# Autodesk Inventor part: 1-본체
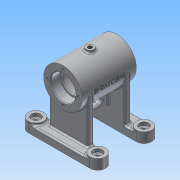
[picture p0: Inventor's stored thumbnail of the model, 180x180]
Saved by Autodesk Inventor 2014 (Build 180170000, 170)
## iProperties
Created: 2015-11
Part Number: 1-본체
Material: 알루미늄 6061
Document SubType Name: Modeling
Designer: 103-09
Density: 2.71 g/cm^3
Appearance: 알루미늄 - 평지
Mass: 359.022 g
Surface Area: 459.449 cm^2
Volume: 132.48 cm^3
Author: 103-09
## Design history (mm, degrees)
sketch "스케치1"
  geometry: L1 (-40, 0)-(40, 0); L2 (-40, 20)-(40, 20); L3 (40, 40)-(-40, 40); L4 (-40, -40)-(40, -40); L5 (40, -20)-(-40, -20); A1 r 10 centre (40, 30) between (40, 20) and (40, 40); A2 r 10 centre (-40, 30) between (-40, 40) and (-40, 20); A3 r 10 centre (40, -30) between (40, -40) and (40, -20); A4 r 10 centre (-40, -30) between (-40, -20) and (-40, -40); 2 further points
  constraints: 10 end point, 8 point on circle, 8 tangent, 4 centre point, 3 parallel, 2 coincident, 1 horizontal, 1 midpoint, 1 vertical alignment
  dimensions: "d2" = 80 distance of A1.centre A2.centre; "d3" = 40 horizontal distance of point (0, 0) A2.centre; "d4" = 20 distance between parallel lines of L2 L3; "d5" = 40 distance between parallel lines of L1 L3; "d6" = 80 distance of A3.centre A4.centre; "d7" = 20 distance between parallel lines of L4 L5; "d8" = 40 distance between parallel lines of L1 L4
extrude "돌출1" new body sketch "스케치1" distance "d9" = 10; taper "d10" = 0 deg
sketch "스케치2"
  geometry: L1 (-40, 20)-(40, 20) reference; L2 (40, 40)-(-40, 40) reference; C1 r 10 at (-40, -30); C2 r 10 at (40, -30); C3 r 10 at (40, 30); C4 r 10 at (-40, 30); A1 r 10 centre (40, -30) between (40, -40) and (40, -20) reference; A2 r 10 centre (-40, -30) between (-40, -20) and (-40, -40) reference; A3 r 10 centre (40, 30) between (40, 20) and (40, 40) reference; A4 r 10 centre (-40, 30) between (-40, 40) and (-40, 20) reference; 1 further point
  constraints: 4 centre point, 4 coincident, 3 equal radius
  dimensions: "d91" = 20 diameter of C4
extrude "돌출2" join sketch "스케치2" distance "d11" = 3; taper "d12" = 0 deg
node "작업 평면1"
sketch "스케치3"
  geometry: L1 (-35, 68)-(35, 68); L2 (-20, 0)-(-40, 0) reference; L3 (-35, 84)-(-23, 84); L4 (-23, 84)-(-23, 82); L5 (-23, 82)-(-21, 82); L6 (-21, 82)-(-21, 89); L7 (-21, 89)-(21, 89); L8 (21, 89)-(21, 82); L9 (21, 82)-(23, 82); L10 (23, 82)-(23, 84); L11 (23, 84)-(35, 84); L12 (35, 84)-(35, 93); L13 (35, 93)-(-35, 93); L14 (-35, 93)-(-35, 84); 2 further points
  constraints: 26 end point, 10 parallel, 3 collinear, 3 vertical alignment, 1 horizontal, 1 midpoint, 1 perpendicular
  dimensions: "d14" = 68 distance between parallel lines of L1 L2; "d15" = 50 diameter of L13 L1; "d16" = 32 diameter of L11 L1; "d17" = 28 diameter of L9 L1; "d18" = 42 diameter of L7 L1; "d19" = 12 distance of L3.start L3.end; "d20" = 70 distance of L12.end L13.end; "d22" = 12 distance of L10.end L11.end; "d23" = 2 distance of L4.end L5.end; "d24" = 42 distance of L6.end L7.end
revolve "회전1" sketch "스케치3" stored, may be unused: angle "d25" = 90 deg
sketch "스케치4"
  geometry: L1 (40, 40)-(-40, 40) reference; L2 (-40, 20)-(40, 20) reference; L3 (-25, 20)-(25, 20); L4 (25, 20)-(25, 28); L5 (25, 28)-(-25, 28); L6 (-25, 28)-(-25, 20); L7 (-40, -40)-(40, -40) reference; L8 (40, -20)-(-40, -20) reference; L9 (-25, -20)-(25, -20); L10 (25, -20)-(25, -28); L11 (25, -28)-(-25, -28); L12 (-25, -28)-(-25, -20); L13 (-4, 20)-(4, 20); L14 (4, -20)-(-4, -20); A1 r 10 centre (-40, -30) between (-40, -20) and (-40, -40) reference; A2 r 10 centre (40, -30) between (40, -40) and (40, -20) reference; 6 further points
  constraints: 20 end point, 5 midpoint, 5 parallel, 3 horizontal, 3 point on line, 3 vertical alignment, 2 equal length, 2 perpendicular, 1 coincident
  dimensions: "d26" = 50 distance of L4.end L5.end; "d27" = 8 distance of L5.end L3.start
extrude "돌출3" join sketch "스케치4" stored distance "d29" = 3; taper "d30" = 0 deg
node "작업 평면4"
sketch "스케치6"
  geometry: L1 (25, 28)-(25, 20) reference; L2 (25, 20)-(-25, 20) reference; L3 (-25, 20)-(-25, 28) reference; L4 (-25, 28)-(25, 28) reference; L5 (25, -20)-(25, -28) reference; L6 (25, -28)-(-25, -28) reference; L7 (-25, -28)-(-25, -20) reference; L8 (-25, -20)-(25, -20) reference; L9 (-4, 20)-(4, 20); L10 (4, 20)-(4, -20); L11 (4, -20)-(-4, -20); L12 (-4, -20)-(-4, 20); 2 further points
  constraints: 8 end point, 2 parallel, 2 point on line, 1 horizontal, 1 midpoint, 1 perpendicular, 1 vertical alignment
  dimensions: "d36" = 8 distance of L9.start L9.end
extrude "돌출5" join sketch "스케치6" stored distance "d37" = 8; taper "d38" = 0 deg
sketch "스케치7"
  geometry: L1 (-20.322, 40)-(0, 40) reference; L2 (-13.5, 12)-(-13.5, 28); L3 (-6.5, 28)-(-6.5, 12); L4 (23, 60)-(23, 40) reference; A1 r 3.5 centre (-10, 28) between (-6.5, 28) and (-13.5, 28); A2 r 3.5 centre (-10, 12) between (-13.5, 12) and (-6.5, 12); 2 further points
  constraints: 4 end point, 4 point on circle, 4 tangent, 2 centre point, 1 horizontal alignment, 1 midpoint, 1 parallel, 1 perpendicular
  dimensions: "d39" = 23 dimension on A1 A2; "d40" = 33 distance from line of A1.centre L4; "d41" = 3.5 radius of A1
extrude "돌출6" cut sketch "스케치7" stored distance "d42" = 8; taper "d43" = 0 deg
node "작업 평면5"
sketch "스케치8"
  geometry: C1 r 5 at (0, 0); 1 further point
  constraints: 1 centre point, 1 coincident
  dimensions: "d45" = 10 diameter of C1
extrude "돌출7" join sketch "스케치8" stored distance "d46" = 8; taper "d47" = 0 deg
node "작업 평면6"
sketch "스케치9"
  geometry: L1 (-4, 23)-(-4, 29.5) reference; L2 (-4, 29.5)-(4, 29.5) reference; L3 (4, 29.5)-(4, 23) reference; L4 (4, 23)-(-4, 23) reference; L5 (-4, 36.5)-(-4, 43.322) reference; L6 (-5, 92.495)-(-5, 96) reference; L7 (-5, 96)-(5, 96) reference; L8 (5, 96)-(5, 92.495) reference; L9 (4, 43.322)-(4, 36.5) reference; L10 (4, 36.5)-(-4, 36.5) reference; L11 (0, 68)-(0, 47); L12 (0, 68)-(14, 43.751); A1 r 25 centre (0, 68) between (-5, 92.495) and (-4, 43.322) reference; A2 r 25 centre (0, 68) between (4, 43.322) and (5, 92.495) reference; 1 further point
  constraints: 4 end point, 1 perpendicular, 1 vertical alignment, 1 other
  dimensions: "d49" = 30 deg angle of L12 L11; "d50" = 28 distance of L11.start L12.end
  node "절단 모서리 투영2"
node "작업 평면7"
sketch "스케치10"
  geometry: C1 r 6 at (0, 0); 1 further point
  constraints: 1 centre point
  dimensions: "d51" = 12 diameter of C1
extrude "돌출8" join sketch "스케치10" stored distance "d52" = 8; taper "d53" = 0 deg
node "작업 평면8"
sketch "스케치11"
  geometry: L1 (-35, 25)-(35, 25) reference; L2 (-35, -25)-(-35, 25) reference; 2 further points
  constraints: 1 other
  dimensions: "d54" = 25 distance from line of L1 point (0, 0); "d55" = 35 distance from line of L2 point (0, 0)
feature "엠보싱1" sketch "스케치11" dims "d56" = 0.5, "d57" = 0
sketch "스케치12"
  geometry: C1 r 25 at (0, 0) reference; C2 r 16 at (0, 0) reference; A1 r 20 centre (0, 0) between (0, 20) and (0, -20); 3 further points
  constraints: 4 point on circle, 2 horizontal alignment, 2 vertical alignment, 1 centre point, 1 coincident
  dimensions: "d58" = 40 diameter of A1
hole "구멍1" sketch "스케치12" at (0, 20), (0, -20), (-20, 0), (20, 0) diameter "d59" = 3.242; stored, may be unused: countersink angle "d63" = 90 deg, drill point angle "d65" = 118 deg; dims "d60" = 8, "d61" = 4, "d62" = 2, "d64" = 10
node "작업 평면9"
hole "구멍2" diameter "d68" = 5.188; stored, may be unused: countersink angle "d72" = 90 deg, drill point angle "d74" = 118 deg; dims "d66" = 10, "d67" = 10, "d69" = 8, "d70" = 4, "d71" = 2, "d73" = 10
hole "구멍3" diameter "d77" = 5.188; stored, may be unused: countersink angle "d81" = 90 deg, drill point angle "d83" = 118 deg; dims "d75" = 10, "d76" = 10, "d78" = 8, "d79" = 4, "d80" = 2, "d82" = 10
chamfer "모따기1" distance "d84" = 1; stored, may be unused: second distance "d85" = 2, angle "d86" = 45 deg
fillet "모깎기1" dims "d87" = 0.3
fillet "모깎기2" dims "d88" = 3
fillet "모깎기3" dims "d89" = 2
fillet "모깎기4" dims "d90" = 2
fillet "모깎기5" dims "d92" = 2
fillet "모깎기6" dims "d93" = 2
fillet "모깎기9" dims "d96" = 2
fillet "모깎기11" dims "d98" = 2
fillet "모깎기12" dims "d99" = 2
fillet "모깎기13" dims "d100" = 2
fillet "모깎기14" dims "d101" = 2
fillet "모깎기15" dims "d102" = 2
fillet "모깎기16" dims "d103" = 2
hole "구멍4" diameter "d106" = 6; stored, may be unused: countersink angle "d110" = 90 deg, drill point angle "d112" = 118 deg; dims "d104" = 10, "d105" = 10, "d107" = 8, "d108" = 12, "d109" = 4, "d111" = 10
fillet "모깎기17" dims "d113" = 0.3
chamfer "모따기2" distance "d114" = 1; stored, may be unused: second distance "d115" = 2, angle "d116" = 45 deg
hole "구멍5" diameter "d119" = 6; stored, may be unused: countersink angle "d123" = 90 deg, drill point angle "d125" = 118 deg; dims "d117" = 10, "d118" = 10, "d120" = 8, "d121" = 12, "d122" = 4, "d124" = 10
hole "구멍6" diameter "d128" = 6; stored, may be unused: countersink angle "d132" = 90 deg, drill point angle "d134" = 118 deg; dims "d126" = 10, "d127" = 10, "d129" = 8, "d130" = 12, "d131" = 4, "d133" = 10
hole "구멍7" diameter "d137" = 6; stored, may be unused: countersink angle "d141" = 90 deg, drill point angle "d143" = 118 deg; dims "d135" = 10, "d136" = 10, "d138" = 8, "d139" = 12, "d140" = 4, "d142" = 10
fillet "모깎기18" dims "d144" = 0.3
chamfer "모따기3" distance "d145" = 1; stored, may be unused: second distance "d146" = 2, angle "d147" = 45 deg
fillet "모깎기19" dims "d148" = 2
fillet "모깎기20" dims "d149" = 2
fillet "모깎기21" dims "d150" = 2
fillet "모깎기22" dims "d151" = 2
node "솔리드1"
mirror "대칭1"
node "투영된 루프1"
node "투영된 루프2"
node "절단 모서리 투영1"
other parameters: "d13" = 0, "d44" = 96, "d48" = 0
